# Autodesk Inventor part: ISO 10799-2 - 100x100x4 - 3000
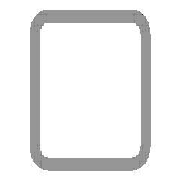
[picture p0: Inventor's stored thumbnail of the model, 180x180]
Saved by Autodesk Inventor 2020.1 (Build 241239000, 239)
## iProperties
Created: 2019-10
Part Number: ISO 10799-2 - 100x100x4 - 3000
Material: Stainless Steel
Description: Structural steels - Cold-formed, welded, structural hollow sections
Document SubType Name: Modeling
Standard: ISO
Designer: Synergysoft Dell02
Standard Revision: First edition 2011-09-15
Standards Organization: ISO
Language: en-US
Size Designation: 100x100x4
Categories: <MemberInstance><Categories><Category DisplayName="Structural Shapes" InternalName="089c4875-fa83-4c05-b084-43b9cc11f5ed" Mnemonic="GRDR"><CategoryParameter Dis
Stock Number: 100x100x4
Density: 8 g/cm^3
Appearance: Semi-Polished
_CCFamilyMember: 43
_CCFamilyDisplayName: ISO 10799-2 (Square) - Structural steels - Cold-formed, welded, structural hollow sections
_FrameMemberDoc: Frame Member File
_Version: 15.0.0
_GetPNFromCC: 1
G_L: 3000.000 mm
G_W: 100.000 mm
G_H: 100.000 mm
IsCustomPart: 1
Author: Synergysoft Dell02
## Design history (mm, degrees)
node "Start Plane"
node "End Plane"
sketch "Sketch"
  geometry: L1 (-50, -42)-(-50, 42); L2 (-42, 50)-(42, 50); L3 (50, 42)-(50, -42); L4 (42, -50)-(-42, -50); L5 (-42, 46)-(42, 46); L6 (46, 42)-(46, -42); L7 (42, -46)-(-42, -46); L8 (-46, -42)-(-46, 42); L9 (0, 72.32)-(0, -72.32) reference; L10 (-72.32, 0)-(72.32, 0) reference; A1 r 8 centre (-42, -42) between (-50, -42) and (-42, -50); A2 r 8 centre (42, 42) between (50, 42) and (42, 50); A3 r 8 centre (-42, 42) between (-42, 50) and (-50, 42); A4 r 8 centre (42, -42) between (42, -50) and (50, -42); A5 r 4 centre (-42, 42) between (-42, 46) and (-46, 42); A6 r 4 centre (42, 42) between (46, 42) and (42, 46); A7 r 4 centre (42, -42) between (42, -46) and (46, -42); A8 r 4 centre (-42, -42) between (-46, -42) and (-42, -46)
  constraints: 16 end point, 16 point on circle, 8 centre point, 8 tangent, 4 parallel, 3 equal radius, 2 perpendicular, 7 other
  dimensions: "d7" = 8 radius of A1 (= G_IR); "d9" = 100 distance between parallel lines of L1 L3 (= G_W); "d11" = 100 distance between parallel lines of L2 L4 (= G_H); "d12" = 4 distance between parallel lines of L3 L6 (= G_T); "d15" = 50 distance between parallel lines of L9 L3 (= 0.5 x d9); "d16" = 50 distance between parallel lines of L2 L10 (= 0.5 x d11)
extrude "Body" new body sketch "Sketch" stored distance "d3" = 3000 (= G_L); taper "d4" = 0 deg
node "Driven Length"
  sketch "Sketch3"
    geometry: L1 (0, 0)-(10, 0) reference
    constraints: 2 end point, 1 horizontal
  workplane "Work Plane3"
  sketch "Sketch4"
    geometry: L1 (-2, 0)-(12, 0) reference; L2 (-2, 3000)-(12, 3000) reference
    dimensions: "d18" = 3000 distance between parallel lines of L1 L2 (derived)
body "Solid1"
other parameters: "G_W" = 100 [user parameter; used in 1 equation term], "G_H" = 100 [user parameter; used in 1 equation term], "G_T" = 4 [user parameter; used in 1 equation term], "G_IR" = 8 [user parameter; used in 1 equation term], "G_L" = 3000 (= d18) [user parameter; used in 1 equation term], "G_OFFSET_START" = 0 [user parameter; used in 1 equation term], "G_OFFSET_END" = 0 [user parameter; used in 1 equation term], "d13" = 0 (computed from G_OFFSET_START), "d17" = 90 deg, "MAS" = 1.17 [user parameter]
